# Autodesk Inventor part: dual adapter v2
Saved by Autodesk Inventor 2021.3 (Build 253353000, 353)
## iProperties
Created: 2022-07
Part Number: dual adapter v2
Material: Generic
Document SubType Name: Modeling
Designer: Administrator
Density: 1 g/cm^3
Appearance: Default
Title: dual adapter v2
Author: Administrator
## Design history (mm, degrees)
